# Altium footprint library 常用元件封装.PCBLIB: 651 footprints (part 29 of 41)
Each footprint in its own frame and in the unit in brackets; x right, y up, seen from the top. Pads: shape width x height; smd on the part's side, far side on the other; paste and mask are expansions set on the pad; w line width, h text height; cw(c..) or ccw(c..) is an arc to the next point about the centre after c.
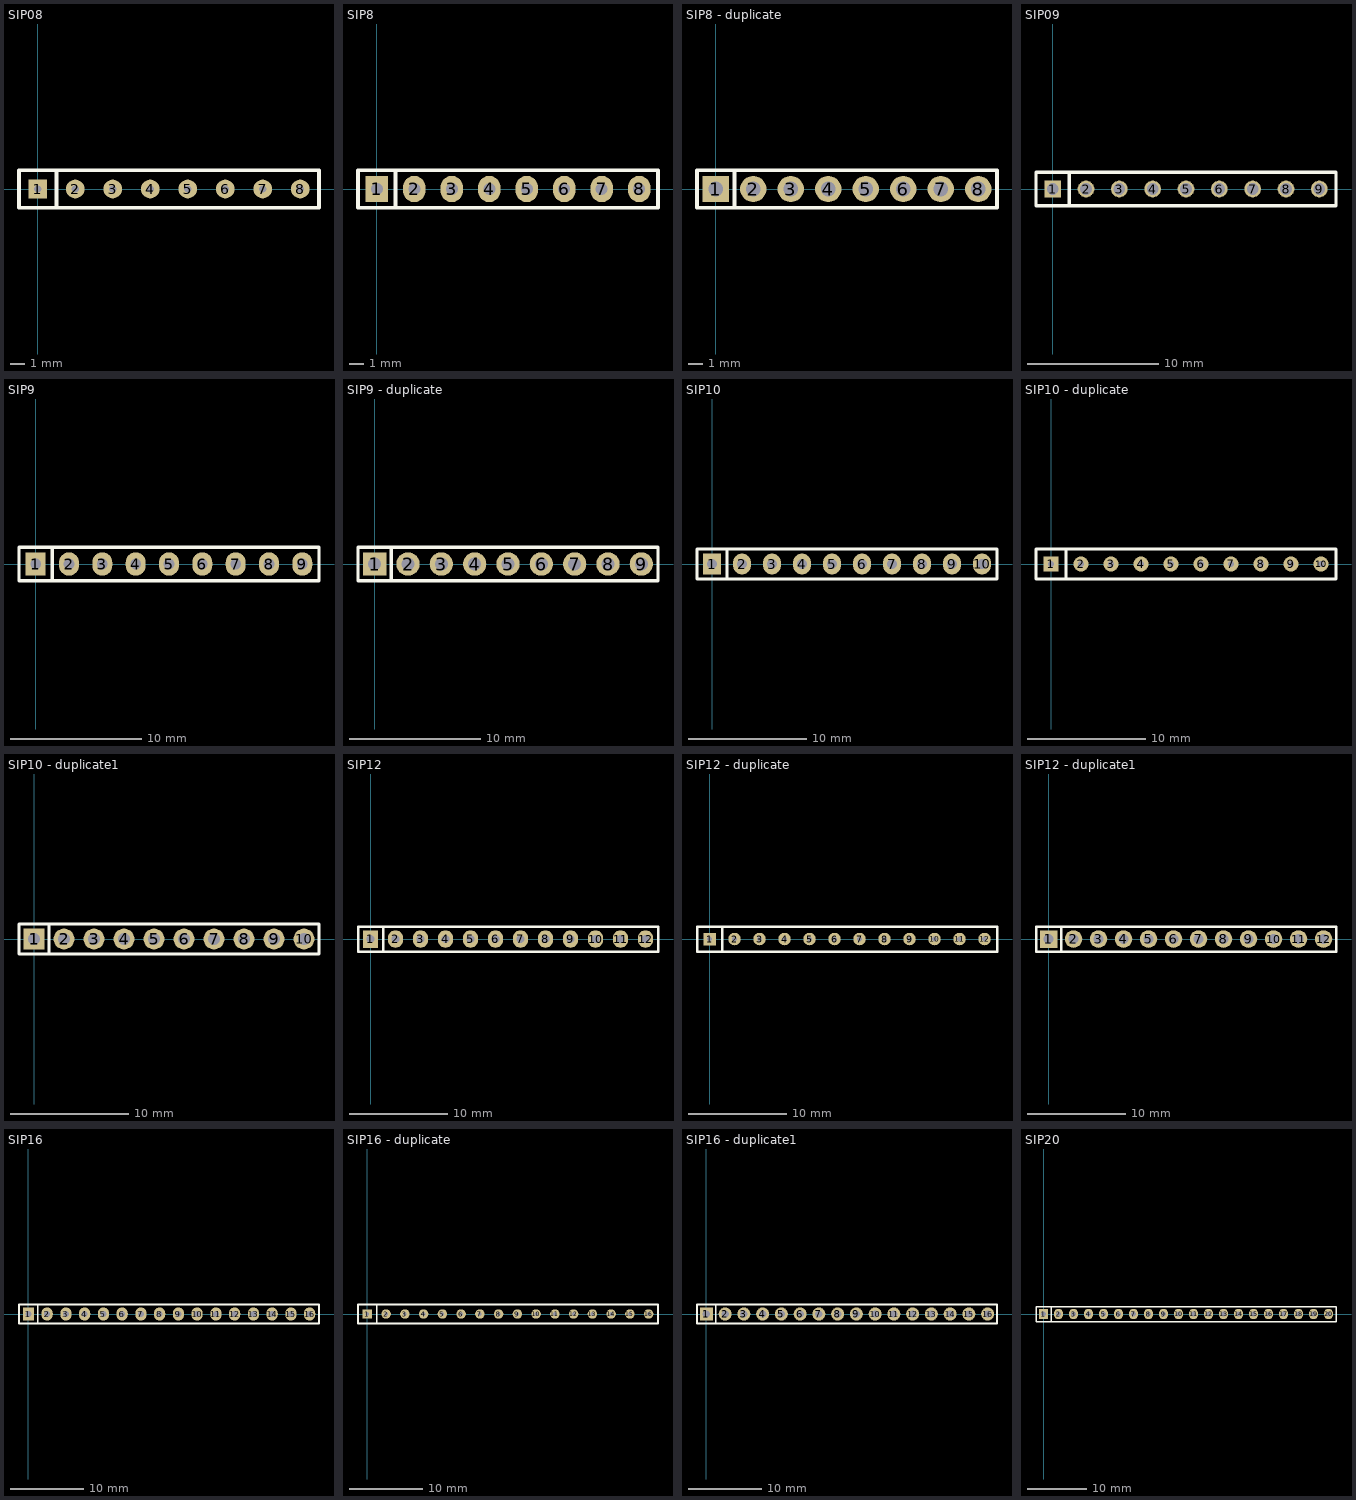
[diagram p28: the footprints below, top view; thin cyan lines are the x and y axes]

## SIP08 [mm]
pads (8):
  rect 1.27x1.27 hole 0.5: 1(0,0)
  round 1.27 hole 0.5: 2(2.54,0) 3(5.08,0) 4(7.62,0) 5(10.16,0) 6(12.7,0) 7(15.24,0) 8(17.78,0)
TopOverlay:
  lines w0.254: 1.27,-1.27 1.27,1.27 ; -1.27,-1.27 19.05,-1.27 19.05,1.27 -1.27,1.27 -1.27,-1.27

## SIP8 [mil]
pads (8):
  rect 60x70 hole 32: 1(0,0)
  oval 60x70 hole 32: 2(100,0) 3(200,0) 4(300,0) 5(400,0) 6(500,0) 7(600,0) 8(700,0)
TopOverlay:
  lines w10: 50,-50 50,50 ; -50,-50 750,-50 750,50 -50,50 -50,-50

## SIP8 - duplicate [mil]
pads (8):
  rect 70x70 hole 39: 1(0,0)
  round 70 hole 39: 2(100,0) 3(200,0) 4(300,0) 5(400,0) 6(500,0) 7(600,0) 8(700,0)
TopOverlay:
  lines w10: 50,-50 50,50 ; -50,-50 750,-50 750,50 -50,50 -50,-50

## SIP09 [mm]
pads (9):
  rect 1.27x1.27 hole 0.9: 1(0,0)
  round 1.27 hole 0.9: 2(2.54,0) 3(5.08,0) 4(7.62,0) 5(10.16,0) 6(12.7,0) 7(15.24,0) 8(17.78,0) 9(20.32,0)
TopOverlay:
  lines w0.254: 1.27,-1.27 1.27,1.27 ; -1.27,-1.27 -1.27,1.27 21.59,1.27 21.59,-1.27 -1.27,-1.27

## SIP9 [mil]
pads (9):
  rect 60x70 hole 32: 1(0,0)
  oval 60x70 hole 32: 2(100,0) 3(200,0) 4(300,0) 5(400,0) 6(500,0) 7(600,0) 8(700,0) 9(800,0)
TopOverlay:
  lines w10: 50,-50 50,50 ; -50,-50 -50,50 850,50 850,-50 -50,-50

## SIP9 - duplicate [mil]
pads (9):
  rect 70x70 hole 39: 1(0,0)
  round 70 hole 39: 2(100,0) 3(200,0) 4(300,0) 5(400,0) 6(500,0) 7(600,0) 8(700,0) 9(800,0)
TopOverlay:
  lines w10: 50,-50 50,50 ; -50,-50 -50,50 850,50 850,-50 -50,-50

## SIP10 [mil]
pads (10):
  rect 60x70 hole 32: 1(0,0)
  oval 60x70 hole 32: 2(100,0) 3(200,0) 4(300,0) 5(400,0) 6(500,0) 7(600,0) 8(700,0) 9(800,0) 10(900,0)
TopOverlay:
  lines w10: 50,-50 50,50 ; -50,-50 -50,50 950,50 950,-50 -50,-50

## SIP10 - duplicate [mm]
pads (10):
  rect 1.27x1.27 hole 0.5: 1(0,0)
  round 1.27 hole 0.5: 2(2.54,0) 3(5.08,0) 4(7.62,0) 5(10.16,0) 6(12.7,0) 7(15.24,0) 8(17.78,0) 9(20.32,0) 10(22.86,0)
TopOverlay:
  lines w0.254: 1.27,-1.27 1.27,1.27 ; -1.27,-1.27 24.13,-1.27 24.13,1.27 -1.27,1.27 -1.27,-1.27

## SIP10 - duplicate1 [mil]
pads (10):
  rect 70x70 hole 39: 1(0,0)
  round 70 hole 39: 2(100,0) 3(200,0) 4(300,0) 5(400,0) 6(500,0) 7(600,0) 8(700,0) 9(800,0) 10(900,0)
TopOverlay:
  lines w10: 50,-50 50,50 ; -50,-50 -50,50 950,50 950,-50 -50,-50

## SIP12 [mil]
pads (12):
  rect 60x70 hole 32: 1(0,0)
  oval 60x70 hole 32: 2(100,0) 3(200,0) 4(300,0) 5(400,0) 6(500,0) 7(600,0) 8(700,0) 9(800,0) 10(900,0) 11(1000,0) 12(1100,0)
TopOverlay:
  lines w10: 50,-50 50,50 ; -50,-50 -50,50 1150,50 1150,-50 -50,-50

## SIP12 - duplicate [mm]
pads (12):
  rect 1.27x1.27 hole 0.5: 1(0,0)
  round 1.27 hole 0.5: 2(2.54,0) 3(5.08,0) 4(7.62,0) 5(10.16,0) 6(12.7,0) 7(15.24,0) 8(17.78,0) 9(20.32,0) 10(22.86,0) 11(25.4,0) 12(27.94,0)
TopOverlay:
  lines w0.254: 1.27,-1.27 1.27,1.27 ; -1.27,-1.27 29.21,-1.27 29.21,1.27 -1.27,1.27 -1.27,-1.27

## SIP12 - duplicate1 [mil]
pads (12):
  rect 70x70 hole 39: 1(0,0)
  round 70 hole 39: 2(100,0) 3(200,0) 4(300,0) 5(400,0) 6(500,0) 7(600,0) 8(700,0) 9(800,0) 10(900,0) 11(1000,0) 12(1100,0)
TopOverlay:
  lines w10: 50,-50 50,50 ; -50,-50 1150,-50 1150,50 -50,50 -50,-50

## SIP16 [mil]
pads (16):
  rect 60x70 hole 32: 1(0,0)
  oval 60x70 hole 32: 2(100,0) 3(200,0) 4(300,0) 5(400,0) 6(500,0) 7(600,0) 8(700,0) 9(800,0) 10(900,0) 11(1000,0) 12(1100,0) 13(1200,0) 14(1300,0) 15(1400,0) 16(1500,0)
TopOverlay:
  lines w10: 50,-50 50,50 ; -50,-50 -50,50 1550,50 1550,-50 -50,-50

## SIP16 - duplicate [mm]
pads (16):
  rect 1.27x1.27 hole 0.5: 1(0,0)
  round 1.27 hole 0.5: 2(2.54,0) 3(5.08,0) 4(7.62,0) 5(10.16,0) 6(12.7,0) 7(15.24,0) 8(17.78,0) 9(20.32,0) 10(22.86,0) 11(25.4,0) 12(27.94,0) 13(30.48,0) 14(33.02,0) 15(35.56,0) 16(38.1,0)
TopOverlay:
  lines w0.254: 1.27,-1.27 1.27,1.27 ; -1.27,-1.27 -1.27,1.27 39.37,1.27 39.37,-1.27 -1.27,-1.27

## SIP16 - duplicate1 [mil]
pads (16):
  rect 70x70 hole 39: 1(0,0)
  round 70 hole 39: 2(100,0) 3(200,0) 4(300,0) 5(400,0) 6(500,0) 7(600,0) 8(700,0) 9(800,0) 10(900,0) 11(1000,0) 12(1100,0) 13(1200,0) 14(1300,0) 15(1400,0) 16(1500,0)
TopOverlay:
  lines w10: 50,-50 50,50 ; -50,-50 1550,-50 1550,50 -50,50 -50,-50

## SIP20 [mil]
pads (20):
  rect 60x70 hole 32: 1(0,0)
  oval 60x70 hole 32: 2(100,0) 3(200,0) 4(300,0) 5(400,0) 6(500,0) 7(600,0) 8(700,0) 9(800,0) 10(900,0) 11(1000,0) 12(1100,0) 13(1200,0) 14(1300,0) 15(1400,0) 16(1500,0) 17(1600,0) 18(1700,0) 19(1800,0) 20(1900,0)
TopOverlay:
  lines w10: 50,-50 50,50 ; -50,-50 -50,50 1950,50 1950,-50 -50,-50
